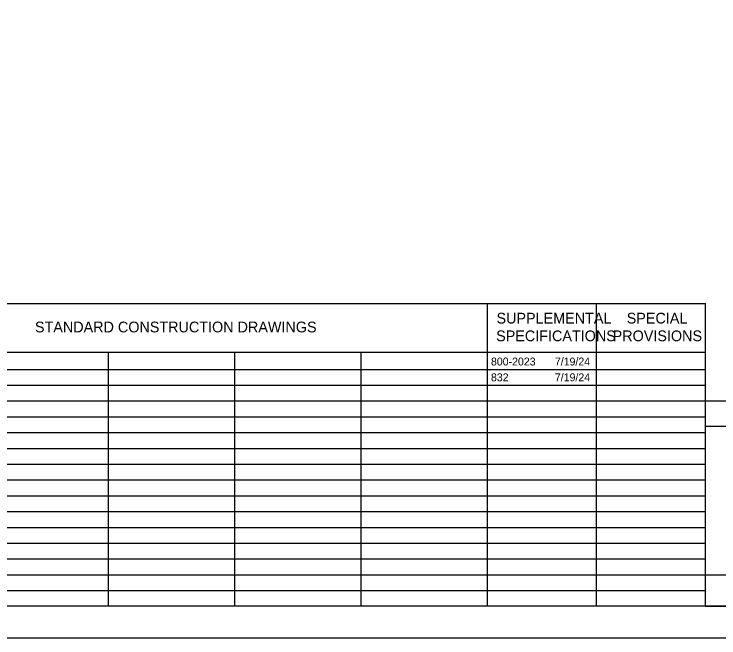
# Model space of a CAD drawing. Extents: x 0 to 68.9, y -26.1 to 22.
# Drawn here: x 12.66 to 23.81, y 0 to 9.87 of the extents above; entities that cross this region are included whole.
import ezdxf

# ---------------------------------------------------------------- set-up
doc = ezdxf.new("R2010")
doc.units = 0
for name, color, linetype in [('SH_Border', 7, 'Continuous'), ('SH_Cut_Line', 7, 'Continuous'), ('SH_Data', 7, 'Continuous'), ('SH_Text', 7, 'Continuous')]:
    doc.layers.add(name, color=color, linetype=linetype)

msp = doc.modelspace()

# ---------------------------------------------------------------- linework, layer by layer
at = {"layer": 'SH_Border'}
msp.add_lwpolyline([(1.5, 21.5), (33.5, 21.5), (33.5, 0.5), (1.5, 0.5)], close=True, dxfattribs=at)
at = {"layer": 'SH_Cut_Line'}
msp.add_lwpolyline([(0, 0), (34, 0), (34, 22), (0, 22)], close=True, dxfattribs=at)
at = {"layer": 'SH_Data'}
for p, q in [((10.15, 5.292), (23.6, 5.292)), ((20.15, 0.5), (20.15, 5.292)), ((21.875, 0.5), (21.875, 5.292)), ((23.6, 0.5), (23.6, 5.292)), ((10.15, 4.521), (23.6, 4.521)), ((14.15, 0.5), (14.15, 4.521)), ((16.15, 0.5), (16.15, 4.521)), ((18.15, 0.5), (18.15, 4.521)), ((10.15, 4.25), (23.6, 4.25)), ((10.15, 4), (23.6, 4)), ((10.15, 3.75), (23.6, 3.75)), ((23.6, 0.5), (23.6, 3.75)), ((23.6, 3.75), (26.4, 3.75)), ((10.15, 3.5), (23.6, 3.5)), ((23.6, 3.35), (26.4, 3.35)), ((10.15, 3.25), (23.6, 3.25)), ((10.15, 3), (23.6, 3)), ((10.15, 2.75), (23.6, 2.75)), ((10.15, 2.5), (23.6, 2.5)), ((10.15, 2.25), (23.6, 2.25)), ((10.15, 2), (23.6, 2)), ((10.15, 1.75), (23.6, 1.75)), ((10.15, 1.5), (23.6, 1.5)), ((10.15, 1.25), (23.6, 1.25)), ((10.15, 1), (23.6, 1)), ((10.15, 0.75), (23.6, 0.75)), ((23.6, 0.5), (26.4, 0.5))]:
    msp.add_line(p, q, dxfattribs=at)
msp.add_lwpolyline([(23.6, 0.5), (23.6, 1), (26.4, 1), (26.4, 0.5)], close=True, dxfattribs=at)

# ---------------------------------------------------------------- texts
at = {"layer": 'SH_Text'}
for s, height, p in [('SUPPLEMENTAL', 0.17, (20.293, 4.976)), ('SPECIAL', 0.17, (22.354, 4.976)), ('STANDARD CONSTRUCTION DRAWINGS', 0.17, (12.986, 4.836)), ('SPECIFICATIONS', 0.17, (20.287, 4.696)), ('PROVISIONS', 0.17, (22.132, 4.696)), ('800-2023', 0.125, (20.205, 4.312)), ('7/19/24', 0.125, (21.217, 4.312)), ('832', 0.125, (20.205, 4.062)), ('7/19/24', 0.125, (21.217, 4.062))]:
    msp.add_text(s, height=height, dxfattribs=at).set_placement(p)

doc.saveas('drawing.dxf')
